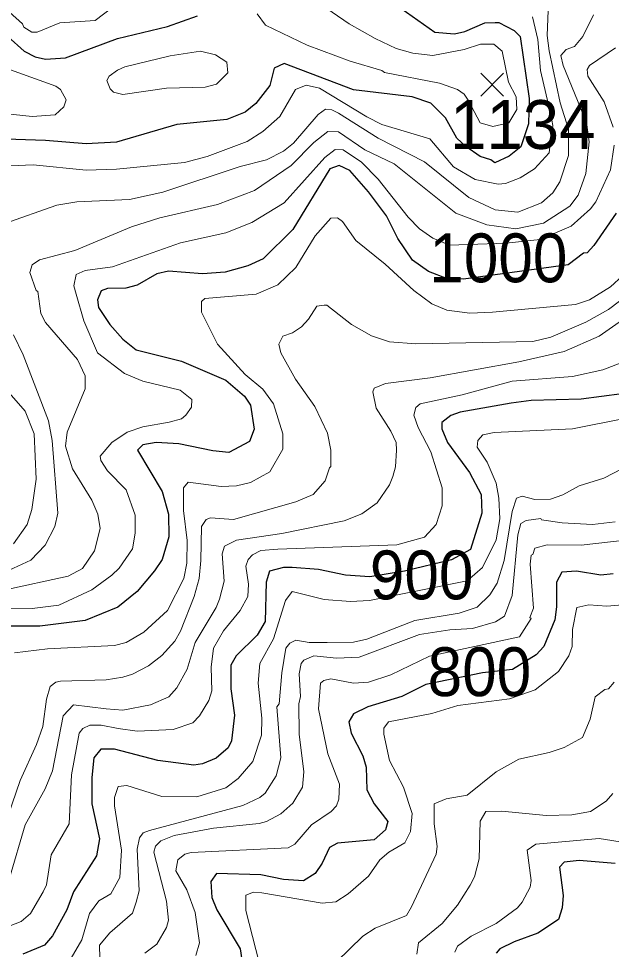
# Model space of a CAD drawing. Extents: x 423 to 448.8, y 7456.3 to 7484.
# Drawn here: x 433.61 to 434.58, y 7468.258 to 7469.783 of the extents above; entities that cross this region are included whole.
import ezdxf
from ezdxf.enums import TextEntityAlignment as Align

# ---------------------------------------------------------------- set-up
doc = ezdxf.new("R2010")
doc.units = 0
doc.header["$LTSCALE"] = 0.032
for name, color, linetype, lineweight in [('1', 7, 'Continuous', 25), ('2', 7, 'Continuous', 13), ('21', 7, 'Continuous', 25)]:
    doc.layers.add(name, color=color, linetype=linetype, lineweight=lineweight)
doc.layers.add('61', color=7, linetype='Continuous')

msp = doc.modelspace()

# ---------------------------------------------------------------- linework, layer by layer
at = {"layer": '1'}
for points in [[(434.1889, 7469.8331), (434.291, 7469.7604), (434.3235, 7469.7581), (434.3405, 7469.7619), (434.373, 7469.7759), (434.39, 7469.7766), (434.3962, 7469.7766), (434.421, 7469.7635), (434.431, 7469.7534), (434.4457, 7469.6521), (434.4448, 7469.6104), (434.4321, 7469.5729), (434.4128, 7469.5572), (434.3895, 7469.5465), (434.3831, 7469.5515), (434.3652, 7469.557), (434.342, 7469.5732), (434.3273, 7469.5871), (434.3088, 7469.6204), (434.2848, 7469.6444), (434.2539, 7469.6544), (434.158, 7469.666), (434.0443, 7469.7093), (434.028, 7469.7016), (434.021, 7469.673), (433.9979, 7469.6436), (433.9808, 7469.6297), (433.9507, 7469.6173), (433.8687, 7469.6096), (433.7697, 7469.5802), (433.7202, 7469.5778), (433.6537, 7469.5833), (433.5717, 7469.5856)], [(433.5918, 7469.7534), (433.6189, 7469.7295), (433.6367, 7469.7202), (433.6537, 7469.7163), (433.6862, 7469.7186), (433.7713, 7469.7503), (433.8532, 7469.7697), (433.9027, 7469.7874)], [(434.588, 7469.4642), (434.5517, 7469.4108), (434.5408, 7469.3992), (434.5344, 7469.3986), (434.5097, 7469.3796), (434.3383, 7469.3556), (434.3119, 7469.3566), (434.2809, 7469.3683), (434.2546, 7469.3868), (434.2307, 7469.4224), (434.2121, 7469.4595), (434.1827, 7469.4989), (434.1518, 7469.5338), (434.1347, 7469.5423), (434.1193, 7469.5368), (434.0589, 7469.4371), (434.0102, 7469.3891), (433.9847, 7469.3775), (433.9476, 7469.3675), (433.9105, 7469.3644), (433.8548, 7469.369), (433.8362, 7469.3644), (433.8037, 7469.3458), (433.7852, 7469.3412), (433.755, 7469.3404), (433.7449, 7469.3365), (433.7387, 7469.3219), (433.7403, 7469.3095), (433.7588, 7469.2816), (433.7805, 7469.2576), (433.8022, 7469.2399), (433.8764, 7469.2213), (433.9491, 7469.1903), (433.9793, 7469.1641), (433.9893, 7469.1494), (433.9955, 7469.1099), (433.9878, 7469.0898), (433.9538, 7469.072), (433.9275, 7469.0743), (433.8718, 7469.0859), (433.8347, 7469.0883), (433.813, 7469.0844), (433.8045, 7469.0759), (433.8447, 7469.0078), (433.8548, 7468.9707), (433.8556, 7468.9336), (433.8447, 7468.8965), (433.8323, 7468.8779), (433.8037, 7468.8438), (433.772, 7468.8183), (433.7187, 7468.7967), (433.6444, 7468.7874), (433.5702, 7468.7874)], [(434.5973, 7469.1679), (434.5308, 7469.1594), (434.4488, 7469.1571), (434.4163, 7469.1525), (434.3328, 7469.1378), (434.3173, 7469.1323), (434.3026, 7469.1208), (434.3026, 7469.1107), (434.3119, 7469.0883), (434.3482, 7469.0388), (434.3668, 7469.0032)], [(434.3668, 7469.0032), (434.3684, 7468.9723), (434.3498, 7468.9127), (434.3186, 7468.8958), (434.2417, 7468.8774), (434.1849, 7468.8681), (434.1447, 7468.8706), (434.1008, 7468.8802), (434.0574, 7468.8833), (434.0435, 7468.8833), (434.0203, 7468.8771), (434.0149, 7468.8593), (434.0133, 7468.7951), (434.0002, 7468.7727), (433.9661, 7468.7387), (433.9569, 7468.7232), (433.9569, 7468.6845), (433.9631, 7468.6412), (433.9584, 7468.5994), (433.953, 7468.5878), (433.9329, 7468.5708), (433.9105, 7468.5615), (433.8966, 7468.5592), (433.8378, 7468.5669), (433.7666, 7468.5855), (433.7442, 7468.5855), (433.7326, 7468.5716), (433.7295, 7468.5391), (433.7294, 7468.4958), (433.7418, 7468.4386), (433.7372, 7468.4107), (433.6993, 7468.3519), (433.6885, 7468.3225), (433.6653, 7468.28), (433.6521, 7468.2645), (433.6166, 7468.2498)], [(434.5834, 7468.8732), (434.5633, 7468.8709), (434.5231, 7468.8771), (434.4991, 7468.8755), (434.4906, 7468.8593), (434.4906, 7468.8191), (434.4875, 7468.7975), (434.4697, 7468.7541), (434.4573, 7468.7402), (434.4184, 7468.7163), (434.3695, 7468.7106), (434.2763, 7468.6915), (434.2369, 7468.6721), (434.1812, 7468.6551), (434.1579, 7468.6435), (434.1502, 7468.6304), (434.1541, 7468.6118), (434.1734, 7468.5747), (434.1789, 7468.5561), (434.1796, 7468.519), (434.192, 7468.4958), (434.2144, 7468.4672), (434.2106, 7468.4532), (434.192, 7468.437), (434.1316, 7468.4316), (434.1185, 7468.4246), (434.1069, 7468.3991), (434.0953, 7468.3821)], [(434.5865, 7468.3983), (434.5277, 7468.403), (434.5029, 7468.4006), (434.4952, 7468.3922), (434.5014, 7468.3458), (434.4998, 7468.3256), (434.4937, 7468.3063), (434.4596, 7468.2839), (434.421, 7468.2699), (434.3977, 7468.2583), (434.3916, 7468.2514)], [(434.0953, 7468.3821), (434.076, 7468.3697), (434.0435, 7468.372), (434.0064, 7468.3797), (433.9337, 7468.3821), (433.9244, 7468.3689), (433.9259, 7468.3426), (433.9344, 7468.3225), (433.9723, 7468.2583), (433.977, 7468.2297)]]:
    msp.add_lwpolyline(points, dxfattribs=at)
at = {"layer": '2'}
for points in [[(433.5949, 7469.7936), (433.6158, 7469.7743), (433.6181, 7469.7689), (433.6312, 7469.7604), (433.6398, 7469.7604), (433.6769, 7469.7758), (433.7349, 7469.7797), (433.7875, 7469.82)], [(434.4774, 7469.8099), (434.4751, 7469.755), (434.4782, 7469.7302), (434.4964, 7469.6446), (434.5099, 7469.6018), (434.5099, 7469.5585), (434.496, 7469.5152), (434.4843, 7469.4974), (434.4658, 7469.4812), (434.4271, 7469.4657), (434.39, 7469.4696), (434.3467, 7469.4897), (434.274, 7469.5484), (434.1982, 7469.5871), (434.1332, 7469.6281), (434.1224, 7469.6335), (434.1123, 7469.6343), (434.0999, 7469.6258), (434.0597, 7469.5786), (434.0435, 7469.5655), (434.0157, 7469.5515), (433.9724, 7469.5407), (433.8455, 7469.4982), (433.7914, 7469.4866), (433.7047, 7469.4827), (433.6723, 7469.4773), (433.5856, 7469.4464)], [(434.0002, 7469.7906), (434.0141, 7469.772), (434.0822, 7469.7395), (434.1525, 7469.7132), (434.2044, 7469.6977), (434.209, 7469.6946), (434.2988, 7469.6768), (434.3281, 7469.6668), (434.339, 7469.659), (434.3459, 7469.649), (434.3653, 7469.6119), (434.3863, 7469.606), (434.4126, 7469.612), (434.4256, 7469.6338), (434.4246, 7469.6548), (434.4118, 7469.6788), (434.4016, 7469.7294), (434.3877, 7469.7411), (434.366, 7469.741), (434.339, 7469.7325), (434.2879, 7469.7225), (434.2554, 7469.7263), (434.2276, 7469.7341), (434.1936, 7469.7503), (434.151, 7469.7743), (434.1038, 7469.8068)], [(434.4511, 7469.7859), (434.4596, 7469.7488), (434.464, 7469.6979), (434.4813, 7469.625), (434.4843, 7469.6077), (434.4797, 7469.5725), (434.4782, 7469.5631), (434.4542, 7469.5369), (434.431, 7469.5222), (434.407, 7469.5129), (434.3947, 7469.5113), (434.3575, 7469.5191), (434.3219, 7469.54), (434.2832, 7469.5856), (434.2044, 7469.6095), (434.1796, 7469.6219), (434.1023, 7469.6691), (434.0806, 7469.6738), (434.0628, 7469.6668), (434.0373, 7469.6227), (434.0094, 7469.598), (433.9839, 7469.5817), (433.9182, 7469.5569), (433.8811, 7469.5469), (433.7697, 7469.5361), (433.7202, 7469.5345), (433.6336, 7469.5431), (433.5965, 7469.5415)], [(434.5509, 7469.789), (434.5338, 7469.7534), (434.52, 7469.7372), (434.506, 7469.7325), (434.4975, 7469.7225), (434.5011, 7469.706), (434.5394, 7469.6125), (434.5439, 7469.5809), (434.5385, 7469.5291), (434.5261, 7469.4935), (434.5122, 7469.4757), (434.4689, 7469.4479), (434.4241, 7469.4386), (434.3761, 7469.4448), (434.3258, 7469.4642), (434.2245, 7469.5446), (434.1766, 7469.5678), (434.1332, 7469.5972), (434.1162, 7469.598), (434.093, 7469.5801), (434.0559, 7469.5423), (433.9956, 7469.5013), (433.9352, 7469.4781), (433.8409, 7469.4564), (433.7945, 7469.4417), (433.7016, 7469.403), (433.6436, 7469.3876), (433.632, 7469.3791)], [(434.5872, 7469.7349), (434.5447, 7469.7062), (434.5408, 7469.6993), (434.5416, 7469.6885), (434.5687, 7469.6467), (434.5834, 7469.6049)], [(433.5609, 7469.7117), (433.6707, 7469.6722), (433.6784, 7469.6668), (433.6877, 7469.6498), (433.6838, 7469.6382), (433.6692, 7469.625), (433.632, 7469.6227), (433.5702, 7469.6289)], [(434.5849, 7469.5756), (434.5787, 7469.5353), (434.5547, 7469.4827), (434.5462, 7469.4713), (434.5146, 7469.4428), (434.4636, 7469.421), (434.4081, 7469.415), (434.315, 7469.4116), (434.2879, 7469.4231), (434.2662, 7469.4386), (434.2477, 7469.4572), (434.1982, 7469.5198), (434.1711, 7469.5477), (434.141, 7469.5678), (434.1278, 7469.5686), (434.1108, 7469.5554), (434.0443, 7469.4812), (433.9917, 7469.4487), (433.9492, 7469.4317), (433.8749, 7469.4154)], [(434.5989, 7469.362), (434.5787, 7469.3435), (434.5447, 7469.3219), (434.5215, 7469.3141), (434.3854, 7469.3017), (434.3483, 7469.3002), (434.3111, 7469.3048), (434.2864, 7469.3156), (434.2569, 7469.3373), (434.2098, 7469.3806), (434.1618, 7469.4193), (434.1402, 7469.4502), (434.1317, 7469.4564), (434.1208, 7469.4556), (434.0953, 7469.427), (434.0636, 7469.3752), (434.0342, 7469.3466), (433.9987, 7469.3311), (433.9143, 7469.3242), (433.9089, 7469.3195), (433.9089, 7469.3017), (433.9352, 7469.2491), (433.9808, 7469.1996), (434.0094, 7469.1756), (434.0272, 7469.1517), (434.042, 7469.1022), (434.042, 7469.0774), (434.0211, 7469.0403), (433.9894, 7469.0225), (433.9662, 7469.0171), (433.9414, 7469.0163), (433.8872, 7469.0233), (433.8795, 7469.014), (433.8795, 7468.9769)], [(433.8749, 7469.4154), (433.7635, 7469.376), (433.7187, 7469.3698), (433.7039, 7469.3636), (433.7001, 7469.3451), (433.7039, 7469.3311), (433.7163, 7469.2878), (433.7388, 7469.2352), (433.7828, 7469.2012), (433.813, 7469.1888), (433.8741, 7469.1741), (433.8935, 7469.1586), (433.8927, 7469.1463), (433.8834, 7469.1331), (433.8764, 7469.1269), (433.8563, 7469.1215), (433.813, 7469.1138), (433.7875, 7469.1053), (433.762, 7469.0882), (433.7434, 7469.0658), (433.7442, 7469.0589), (433.755, 7469.0419), (433.7859, 7469.0109), (433.8006, 7468.9692), (433.8006, 7468.9398), (433.796, 7468.9142), (433.7744, 7468.8825), (433.762, 7468.8709), (433.7295, 7468.8469), (433.6753, 7468.8214), (433.632, 7468.816), (433.5485, 7468.8175)], [(433.632, 7469.3791), (433.6281, 7469.3667), (433.6382, 7469.3373), (433.6413, 7469.3358), (433.646, 7469.2994), (433.6537, 7469.2847), (433.7062, 7469.2244), (433.7187, 7469.1973), (433.7187, 7469.1764), (433.6893, 7469.1053), (433.6862, 7469.0821), (433.6977, 7469.045), (433.7294, 7468.9939), (433.7395, 7468.9707), (433.7434, 7468.9475), (433.7341, 7468.9104), (433.714, 7468.8817), (433.6908, 7468.8694), (433.5856, 7468.8461)], [(433.5926, 7468.4772), (433.6119, 7468.5345), (433.639, 7468.5933), (433.649, 7468.6227), (433.6552, 7468.6675), (433.6614, 7468.6884), (433.6707, 7468.6953), (433.6784, 7468.6969), (433.7527, 7468.6992), (433.7805, 7468.7038), (433.796, 7468.7085), (433.8223, 7468.7224), (433.844, 7468.7394), (433.8656, 7468.7626), (433.8749, 7468.7789), (433.8973, 7468.8361), (433.905, 7468.8655), (433.9081, 7468.8949), (433.9089, 7468.9506), (433.9167, 7468.9622), (433.9236, 7468.9645), (433.9615, 7468.9622), (434.0636, 7468.9908), (434.0922, 7469.0032), (434.1116, 7469.0256), (434.1185, 7469.0465), (434.1209, 7469.0488), (434.1209, 7469.0759), (434.1154, 7469.1037), (434.0945, 7469.1471), (434.0628, 7469.1919), (434.0389, 7469.2352), (434.0358, 7469.2492), (434.042, 7469.2623), (434.0582, 7469.2677), (434.0729, 7469.2778), (434.0845, 7469.2901), (434.0977, 7469.3118), (434.11, 7469.3133), (434.1146, 7469.3133), (434.1548, 7469.2816), (434.1874, 7469.263), (434.2168, 7469.253), (434.2601, 7469.2499), (434.4519, 7469.2538), (434.4813, 7469.2607), (434.5385, 7469.2855), (434.5757, 7469.3063), (434.6453, 7469.3589)], [(434.6298, 7469.311), (434.5602, 7469.2623), (434.503, 7469.2375), (434.4287, 7469.2205), (434.2833, 7469.1942), (434.2106, 7469.1849), (434.192, 7469.1772), (434.1897, 7469.171), (434.1951, 7469.1447), (434.2191, 7469.1068), (434.2276, 7469.0882), (434.2283, 7469.0759), (434.2268, 7469.0481), (434.2222, 7469.0326), (434.2167, 7469.0187), (434.1966, 7468.9893), (434.1719, 7468.9714), (434.1425, 7468.9598), (434.0404, 7468.939), (433.9662, 7468.9281), (433.9468, 7468.9181), (433.943, 7468.9057), (433.9461, 7468.8609), (433.9383, 7468.8315), (433.9329, 7468.8176), (433.8988, 7468.7603), (433.8857, 7468.717), (433.8687, 7468.6861), (433.8556, 7468.6713), (433.8254, 7468.6582), (433.7805, 7468.6497), (433.7527, 7468.652), (433.6993, 7468.6582), (433.6823, 7468.6404), (433.6653, 7468.5499), (433.6529, 7468.5206), (433.6204, 7468.4617), (433.5949, 7468.3743)], [(433.6011, 7469.2646), (433.6173, 7469.2321), (433.6583, 7469.1239), (433.6645, 7469.0914), (433.6738, 7468.9723), (433.6691, 7468.9506), (433.6529, 7468.9197), (433.6297, 7468.8956), (433.5872, 7468.8755)], [(433.5841, 7468.2916), (433.6135, 7468.3032), (433.6289, 7468.3163), (433.6498, 7468.3519), (433.6552, 7468.3635), (433.663, 7468.4123), (433.6923, 7468.4633), (433.6962, 7468.5438), (433.7086, 7468.6118), (433.7148, 7468.6195), (433.7264, 7468.6249), (433.745, 7468.6249), (433.7728, 7468.6196), (433.8037, 7468.6149), (433.8625, 7468.618), (433.895, 7468.6288), (433.9058, 7468.6404), (433.9213, 7468.6652), (433.9259, 7468.6814), (433.9251, 7468.7201), (433.929, 7468.751), (433.9453, 7468.7796), (433.9724, 7468.8129), (433.9847, 7468.8361), (433.9862, 7468.8562), (433.9816, 7468.8856), (433.9855, 7468.8965), (433.9924, 7468.9041), (434.0064, 7468.9111), (434.0342, 7468.9135), (434.2291, 7468.9204), (434.274, 7468.9328), (434.2933, 7468.9537), (434.3034, 7468.9846), (434.3034, 7469.014), (434.2848, 7469.0728), (434.2639, 7469.113), (434.257, 7469.1331), (434.2601, 7469.1455), (434.267, 7469.1517), (434.3359, 7469.1664), (434.4179, 7469.1888), (434.5169, 7469.1966), (434.5664, 7469.2074), (434.6205, 7469.2282)], [(433.5748, 7469.1911), (433.6204, 7469.1393), (433.6351, 7469.1022), (433.6382, 7469.0279), (433.6312, 7468.9784), (433.6235, 7468.9537), (433.6011, 7468.922)], [(434.602, 7469.1277), (434.5169, 7469.1107), (434.3885, 7469.1045), (434.3699, 7469.1006), (434.3614, 7469.0914), (434.3606, 7469.0805), (434.3768, 7469.0558), (434.3915, 7469.0218), (434.3962, 7468.997), (434.3977, 7468.963), (434.3915, 7468.9289), (434.3691, 7468.8833), (434.3442, 7468.8615), (434.1843, 7468.8291), (434.1533, 7468.8276), (434.11, 7468.8307), (434.0574, 7468.8438), (434.0466, 7468.8291), (434.0272, 7468.7665), (434.0048, 7468.7262), (434.0017, 7468.6938), (434.0079, 7468.6366), (434.0071, 7468.6087), (433.9932, 7468.5654), (433.9693, 7468.5375), (433.9491, 7468.5221), (433.9012, 7468.5074), (433.844, 7468.5082), (433.7867, 7468.5259), (433.7728, 7468.5244), (433.7666, 7468.5066), (433.7666, 7468.4927), (433.7782, 7468.42), (433.7751, 7468.3751), (433.7604, 7468.3488), (433.7411, 7468.3372), (433.7256, 7468.3164), (433.7132, 7468.273), (433.6955, 7468.2429)], [(434.6135, 7469.0534), (434.5679, 7469.0295), (434.5277, 7469.0171), (434.5006, 7469.0024), (434.4805, 7468.9955), (434.455, 7468.9947), (434.4341, 7469.0001), (434.4248, 7468.997), (434.4179, 7468.9753), (434.4047, 7468.8949), (434.3931, 7468.8577), (434.3815, 7468.8384), (434.3606, 7468.8183), (434.3312, 7468.8083), (434.2585, 7468.7966), (434.1796, 7468.7657), (434.158, 7468.7611), (434.1147, 7468.7603), (434.0853, 7468.7603), (434.0636, 7468.7642), (434.0536, 7468.7595), (434.0473, 7468.751), (434.0404, 7468.7108), (434.0365, 7468.6598), (434.0327, 7468.6551), (434.0389, 7468.5716), (434.0311, 7468.5422), (434.0133, 7468.5136), (434.0048, 7468.5066), (433.977, 7468.4935), (433.8239, 7468.4524), (433.8138, 7468.4486), (433.8076, 7468.4401), (433.8037, 7468.4216), (433.8068, 7468.3535), (433.8022, 7468.3349), (433.796, 7468.3171), (433.7589, 7468.2846), (433.7418, 7468.2645), (433.7434, 7468.222)], [(433.8795, 7468.9769), (433.8857, 7468.9274), (433.8849, 7468.8903), (433.8803, 7468.8655), (433.8532, 7468.8129), (433.8145, 7468.7773), (433.7859, 7468.7603), (433.7666, 7468.7557), (433.6568, 7468.7502), (433.6026, 7468.7433)], [(434.5865, 7468.9583), (434.5494, 7468.9537), (434.4999, 7468.9568), (434.4658, 7468.9614), (434.465, 7468.9637), (434.441, 7468.9606), (434.4318, 7468.9552), (434.4271, 7468.9367), (434.4179, 7468.8377), (434.4055, 7468.8036), (434.3908, 7468.7943), (434.3529, 7468.7835), (434.3158, 7468.7812), (434.2663, 7468.7734), (434.1673, 7468.7363), (434.1301, 7468.7348), (434.093, 7468.7387), (434.0767, 7468.7317), (434.0721, 7468.7263), (434.069, 7468.7093), (434.0714, 7468.6722), (434.0683, 7468.6598), (434.069, 7468.6103), (434.0767, 7468.5484), (434.0744, 7468.5236), (434.0589, 7468.4973), (434.0388, 7468.4795), (434.0157, 7468.4672), (434.0033, 7468.4641), (433.929, 7468.4563), (433.8641, 7468.4439), (433.8424, 7468.4354), (433.8339, 7468.4269), (433.8308, 7468.4169), (433.8517, 7468.3364), (433.8548, 7468.3055), (433.8517, 7468.2932), (433.8362, 7468.2661), (433.8161, 7468.2514)], [(434.6747, 7468.9366), (434.5308, 7468.9197), (434.4751, 7468.9204), (434.4549, 7468.915), (434.4519, 7468.9049), (434.4488, 7468.9034), (434.4473, 7468.8887), (434.4526, 7468.8168), (434.4465, 7468.8013), (434.4491, 7468.7996), (434.4296, 7468.7695), (434.2825, 7468.7379), (434.2191, 7468.7077), (434.1827, 7468.6953), (434.158, 7468.6938), (434.1209, 7468.7007), (434.1092, 7468.6984), (434.1038, 7468.6938), (434.1007, 7468.652), (434.1162, 7468.5778), (434.1348, 7468.5283), (434.134, 7468.5035), (434.1301, 7468.4927), (434.1216, 7468.4834), (434.0891, 7468.4617), (434.062, 7468.43), (434.0512, 7468.4238), (433.8919, 7468.4161), (433.8818, 7468.4138), (433.8702, 7468.4045), (433.8672, 7468.386), (433.8849, 7468.355), (433.8988, 7468.3179), (433.9058, 7468.2684), (433.8997, 7468.2475)], [(434.0033, 7468.2359), (433.9816, 7468.321), (433.9816, 7468.3465), (433.994, 7468.3511), (434.0079, 7468.3504), (434.1069, 7468.3333), (434.1293, 7468.3357), (434.1495, 7468.3488), (434.1827, 7468.3774), (434.2013, 7468.4045), (434.216, 7468.4169), (434.2423, 7468.4323), (434.2515, 7468.4509), (434.2539, 7468.4803), (434.24, 7468.5236), (434.2168, 7468.567), (434.2075, 7468.6103), (434.2075, 7468.6203), (434.2152, 7468.6304), (434.2864, 7468.6443), (434.3289, 7468.6574), (434.4132, 7468.6683), (434.4557, 7468.6829), (434.4937, 7468.7131), (434.5106, 7468.7387), (434.5161, 7468.7541), (434.5169, 7468.782), (434.5238, 7468.8176), (434.5432, 7468.8222), (434.5726, 7468.8199), (434.6437, 7468.826)], [(434.5849, 7468.6953), (434.5756, 7468.6845), (434.5695, 7468.6837), (434.554, 7468.6714), (434.5455, 7468.635), (434.5331, 7468.6048), (434.503, 7468.5886), (434.4782, 7468.5801)], [(434.4782, 7468.5801), (434.4287, 7468.5692), (434.3916, 7468.5484), (434.3444, 7468.5105), (434.3096, 7468.5043), (434.2902, 7468.4958), (434.2902, 7468.4633), (434.2949, 7468.4262), (434.2933, 7468.4138), (434.2531, 7468.3272), (434.2446, 7468.3133), (434.1936, 7468.2924), (434.1734, 7468.2792), (434.1301, 7468.2374)], [(434.5826, 7468.5128), (434.5718, 7468.5004), (434.5463, 7468.4834), (434.5153, 7468.478), (434.4736, 7468.4772), (434.4009, 7468.4842), (434.3745, 7468.4834), (434.3652, 7468.4679), (434.3637, 7468.4061), (434.356, 7468.3767), (434.349, 7468.3628), (434.3281, 7468.3302), (434.3034, 7468.3001), (434.2647, 7468.2684), (434.2616, 7468.2498)], [(434.605, 7468.4324), (434.5602, 7468.4393), (434.4565, 7468.43), (434.4426, 7468.42), (434.4488, 7468.3705), (434.4473, 7468.3597), (434.4341, 7468.3349), (434.4264, 7468.3256), (434.3916, 7468.3001), (434.3506, 7468.2792), (434.3281, 7468.263), (434.3242, 7468.2529)]]:
    msp.add_lwpolyline(points, dxfattribs=at)
msp.add_lwpolyline([(433.8517, 7469.6691), (433.9151, 7469.6707), (433.9336, 7469.6753), (433.9522, 7469.6939), (433.9507, 7469.7116), (433.9321, 7469.7233), (433.9074, 7469.7294), (433.8579, 7469.7217), (433.7836, 7469.7039), (433.7713, 7469.6985), (433.7581, 7469.6884), (433.7542, 7469.6815), (433.7596, 7469.6676), (433.765, 7469.6621), (433.7805, 7469.6583)], close=True, dxfattribs=at)
at = {"layer": '21'}
for p, q in [((434.3664, 7469.6933), (434.4039, 7469.6558)), ((434.4039, 7469.6933), (434.3664, 7469.6558))]:
    msp.add_line(p, q, dxfattribs=at)

# ---------------------------------------------------------------- texts
at = {"layer": '61'}
msp.add_text('1134', height=0.08, dxfattribs=at).set_placement((434.4352, 7469.5693), align=Align.CENTER)
at = {"layer": '61', "width": 0.95}
for s, p in [('1000', (434.3952, 7469.3508)), ('900', (434.2696, 7468.8312)), ('800', (434.3642, 7468.6726))]:
    msp.add_text(s, height=0.08, dxfattribs=at).set_placement(p, align=Align.CENTER)

doc.saveas('drawing.dxf')
